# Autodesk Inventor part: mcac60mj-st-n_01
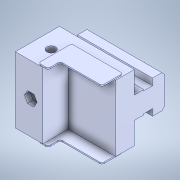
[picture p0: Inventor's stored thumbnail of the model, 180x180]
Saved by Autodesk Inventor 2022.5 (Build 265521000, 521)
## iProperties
Created: 2023-04
Part Number: mcac60mj-st-n_01
Material: Generic
Document SubType Name: Modeling
Designer: ImaoCorp
Density: 1 g/cm^3
Appearance: Default
Author: ImaoCorp
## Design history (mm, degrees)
feature "mcac60mj-st-n_01"
node "ソリッド1"
